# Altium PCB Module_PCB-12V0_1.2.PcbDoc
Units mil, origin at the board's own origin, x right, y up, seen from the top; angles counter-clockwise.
Board outline 2952.76 x 1181.1 mil, 2 copper layers (TopLayer, BottomLayer); 70 components, 40 nets, 211 pads, 102 vias.
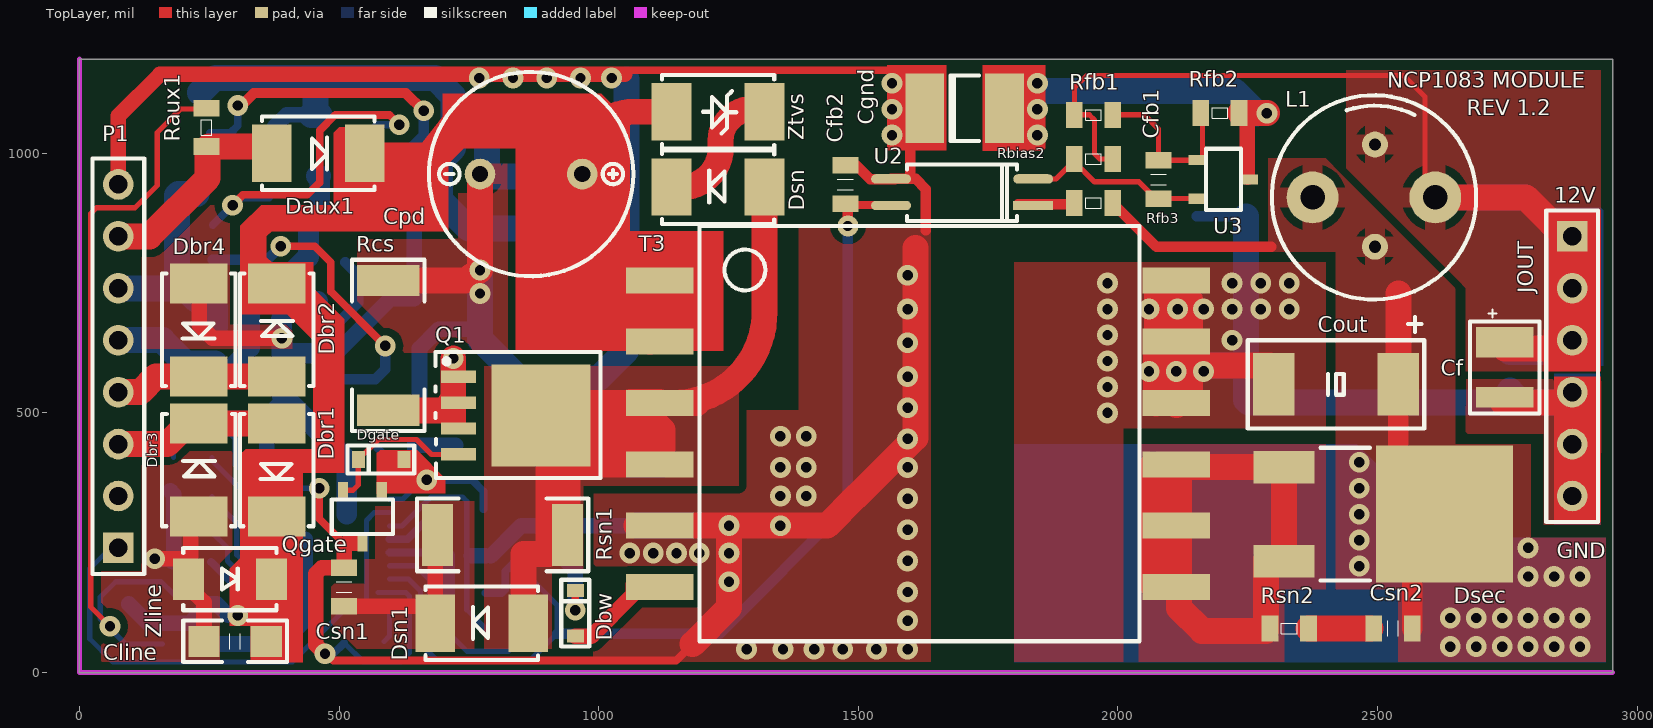
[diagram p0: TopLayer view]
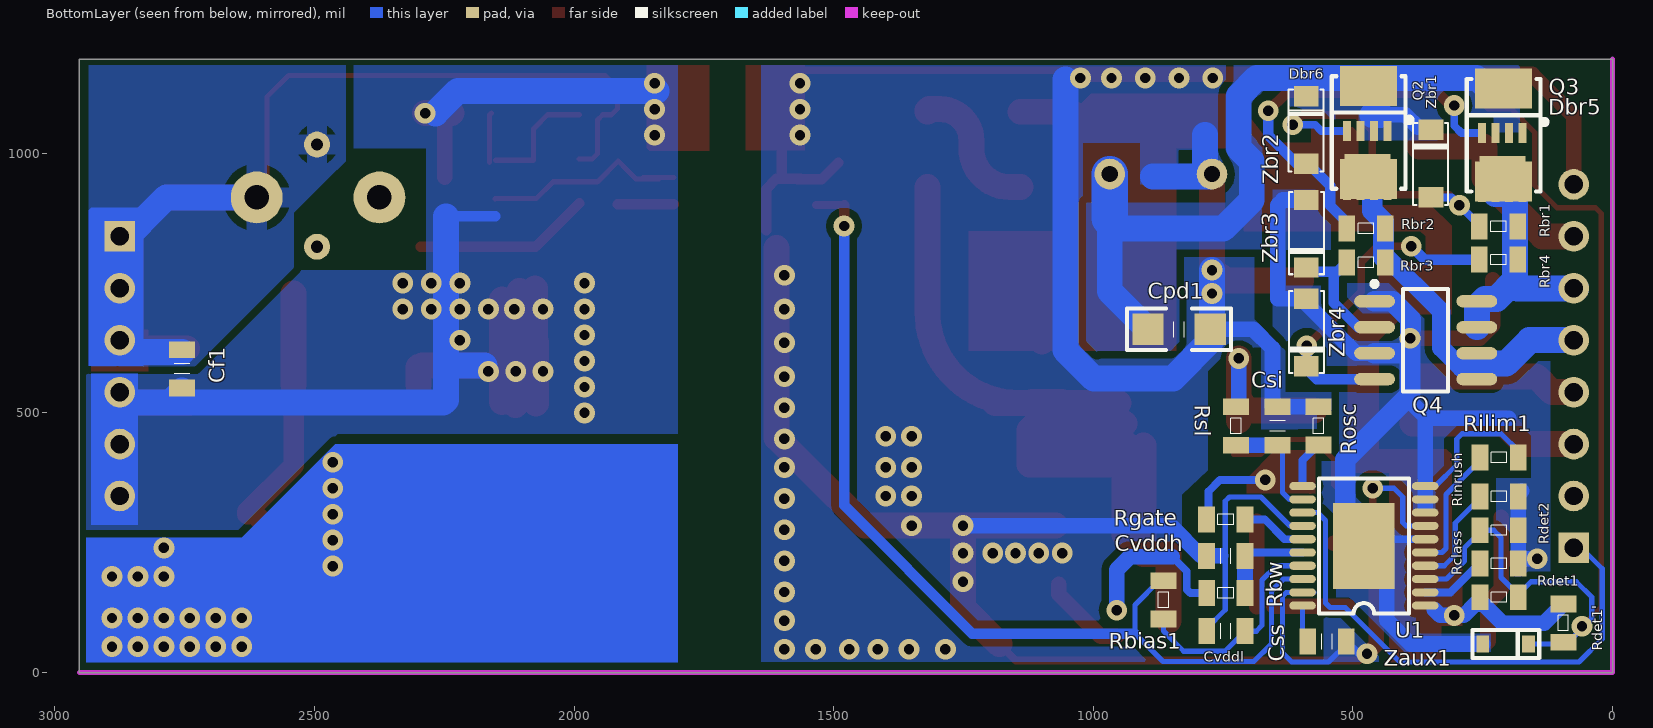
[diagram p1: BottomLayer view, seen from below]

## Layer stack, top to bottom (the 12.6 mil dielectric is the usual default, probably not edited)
TopLayer: signal copper 1.4
Dielectric: core 12.6, FR-4, Dk 4.8
BottomLayer: signal copper 1.4

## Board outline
0,0 0,1181.1 2952.76,1181.1 2952.76,0

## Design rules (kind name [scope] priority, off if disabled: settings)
Clearance Clearance_1 [inpolygon] p1: gap=15
Clearance [All] p2: gap=8
PasteMaskExpansion PasteMaskExpansion_1 [All] p1: expansion=0
PasteMaskExpansion [All] p2: expansion=0
PolygonConnect Thrucomp [All vs InThruComponent] p1: connectstyle=Relief reliefconductorwidth=40 reliefentries=4 polygonreliefangle="90 Angle"
PolygonConnect [All] p2: connectstyle=Direct reliefconductorwidth=10 reliefentries=4 polygonreliefangle="90 Angle"
RoutingVias [All] p1: holewidth=20 width=40 viastyle="Through Hole" minholewidth=20 minwidth=40 maxholewidth=20 maxwidth=40
ShortCircuit ShortCircuit_1 [All] p1: allowed=FALSE
ShortCircuit [All] p2: allowed=FALSE
SolderMaskExpansion SolderMaskExpansion_1 [All] p1: expansion=4
SolderMaskExpansion [All] p2: expansion=2
TestPointUsage [All] p1: valid=0 allowmultiple=FALSE
Testpoint [All] p1: side=7 testpointundercomponent=TRUE minsize=40 maxsize=100 preferedsize=60 minholesize=20 maxholesize=40 preferedholesize=32 testpointgrid=1 style=1001 order=0-112345678
UnRoutedNet UnRoutedNet_1 [All] p1:
UnRoutedNet [All] p2:
Width [All] p1: maxlimit=150 minlimit=8 preferedwidth=10
16 further rules are at their usual default settings.

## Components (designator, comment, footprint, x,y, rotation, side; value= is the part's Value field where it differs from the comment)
Cf "10u/20V" C-TANT-B 2745,530 r90 top
Cf1 "0.1u" 0805-C-S 2755,585 r270 bottom
Cfb1 "39n" 0805-C-S 2078.23,949.69 r270 top
Cfb2 "12n" 0805-C-S 1475,940 r90 top
Cgnd "2200p/2kV" 1812 1704.84,1086.5 r0 top
Cline "100n/100V" 1206-C 300,60 r0 top
Cout "68u/25V/55mR" C-TANT-E 2420,555 r180 top
Cpd "100u/63V" CRD10.0L17.0RM5.0 870,960 r180 top
Cpd1 "100n/100V" 1206-C 835,661 r0 bottom
Csi "NC" 0805-C-S 645,475 r90 bottom
Csn1 "100p/200V" 0805-C-S 510,165 r90 top
Csn2 "470p/200V" 0805-C-S 2530,85 r180 top
Css "47n" 0805-C-S 550,60 r180 bottom
Cvddh "2.2u/16V" 0805-C-S 745.06,224.61 r0 bottom
Cvddl "470n" 0805-C-S 745,80 r0 bottom
Daux1 "MBRS2H100T3G" 403A-03 460,1000 r0 top
Dbr1 "MBRS1100T3G" 403A-03 380,390 r270 top
Dbr2 "MBRS1100T3G" 403A-03 380,660 r90 top
Dbr3 "MBRS1100T3G" 403A-03 230,390 r90 top
Dbr4 "MBRS1100T3G" 403A-03 230,660 r270 top
Dbr5 "MBRS1100T3G" 403A-03_D 210,1035 r90 bottom
Dbr6 "MBRS1100T3G" 403A-03_D 470,1040 r90 bottom
Dbw "BAS16HT1G" SOD323 955,70 r90 top
Dgate "BAS16HT1G" SOD323 625,410 r180 top
Dsec "12CWQ06FNPBF" DPAK 2320,305 r270 top
Dsn "MURS120T3G" 403A-03 1230,935 r180 top
Dsn1 "MURS120T3G" 403A-03 775,95 r180 top
JOUT "Header 6" HDR1X6 2875,840 r270 top
L1 "10uH/3A" 10X12 2375,915 r0 top
P1 "Header 8" HDR1X8 75,240 r90 top
Q1 "Si7462DP" SOPP8 840,495 r0 top
Q2 "Si7113DN" "POWERPACK 1212-8" 472.44,984.25 r270 bottom
Q3 "Si7113DN" "POWERPACK 1212-8" 212.6,980.32 r270 bottom
Q4 "FDS3992" SO-8 360,640 r180 bottom
Qgate "BFT92" SOT23 545,300 r180 top
Raux1 "39k" 0805-R-S 245,1050 r90 top
Rbias1 "5.1k" 0805-R-S 865,140 r270 bottom
Rbias2 "20k" 0805-R-S 1953.23,989.06 r0 top
Rbr1 "150k" 0805-R-S 220,859 r180 bottom
Rbr2 "150k" 0805-R-S 475,855 r180 bottom
Rbr3 "150K" 0805-R-S 475,790 r0 bottom
Rbr4 "150K" 0805-R-S 220,795 r0 bottom
Rbw "75" 0805-R-S 745,153 r0 bottom
Rclass "22" 0805-R-S 218.46,210 r180 bottom
Rcs "0R1/2W" 2512-S 595,630 r270 top
Rdet1 "24.9k/0.1%" 0805-R-S 218.46,145 r180 bottom
Rdet1' "ADJ" 0805-R-S 95,95 r270 bottom
Rdet2 "845/0.1%" 0805-R-S 218.46,274.06 r180 bottom
Rfb1 "15k" 0805-R-S 1953.23,1074.06 r0 top
Rfb2 "3.9k" 0805-R-S 2196.34,1077.8 r180 top
Rfb3 "820" 0805-R-S 1953.23,904.06 r180 top
Rgate "10" 0805-R-S 745.06,294.61 r180 bottom
Rilim1 "44.2K" 0805-R-S 218.46,414.06 r0 bottom
Rinrush "120K" 0805-R-S 218.46,339.06 r0 bottom
Rosc "150K" 0805-R-S 566.24,475.16 r270 bottom
Rsl "5.1k" 0805-R-S 725,475 r270 bottom
Rsn1 "330/2W" 2512-S 815,265 r0 top
Rsn2 "75" 0805-R-S 2330,85 r180 top
T3 "SM-00112" NUFLUX 1615,460 r0 top
U1 "NCP1083" TSSOPEP20 479.06,243.98 r0 bottom
U2 "PS2801-1-F3-A" SSOP4 1700,925 r180 top
U3 "TL432BIDBZTG4" SOT23 2203.23,949.69 r270 top
Zaux1 "MM3Z3V3ST1G" SOD323 250,55 r180 bottom
Zbr1 "MMSZ16T1G" SOD123 350,915 r90 bottom
Zbr2 "MMSZ16T1G" SOD123 590,980 r90 bottom
Zbr3 "MMSZ16T1G" SOD123 590,910 r270 bottom
Zbr4 "MMSZ16T1G" SOD123 590,720 r270 bottom
Zline "1SMA58AT3G" SMA 290,180 r0 top
Ztvs "1SMB100AT3G" 403A-03 1230,1080 r0 top
? "Comment" COILCRAFT_IN 2495,820 r90 top

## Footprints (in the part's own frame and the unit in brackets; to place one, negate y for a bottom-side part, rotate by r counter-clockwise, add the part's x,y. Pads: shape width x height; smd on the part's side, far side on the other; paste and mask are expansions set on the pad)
10X12 [mm]
  round 2.54 hole 1.2: 1(0,0) 2(6,0)
  silkscreen extent -2,-5 8,5
403A-03 [mm] "Molded Diode, 2-Leads, Body 5.3x3.4mm, IPC Medium Density"
  rect 1.95x2.8 smd: 1(-2.275,0) 2(2.275,0)
  silkscreen extent -2.75,-1.8 2.75,1.8
403A-03_D [mm] "Molded Diode, 2-Leads, Body 5.3x3.4mm, IPC Medium Density"
  rect 1.95x2.8 smd: 1(-2.275,0) 2(2.275,0)
  silkscreen extent -2.75,-1.8 2.75,1.8
0805-C-S [mil]
  rect 32x50 smd: 1(-37,0) 2(37,0)
  silkscreen extent -10,-15 10,15
0805-R-S [mil]
  rect 32x50 smd: 1(-37,0) 2(37,0)
  silkscreen extent -15,-10 15,10
1206-C [mil]
  rect 60x60 smd: 1(-60,0) 2(60,0)
  silkscreen extent -100,-40 100,40
1812 [mm] "Chip Capacitor; Body 4.5 x 3.2 mm (LxW typ)"
  rect 1.9x3.4 smd: 1(-1.95,0) 2(1.95,0)
  silkscreen extent -0.7,-1.6 0.7,1.6
2512-S [mil]
  rect 60x120 smd: 1(-125,0) 2(125,0)
  silkscreen extent -165,-70 165,70
C-TANT-B [mm]
  rect 1.5x2.8 smd: 1(2.7,0)
  rect 1x2.8 smd: 2(0,0)
  silkscreen extent -0.8,-1.7 4.3,1.7
C-TANT-E [mil]
  rect 80x120 smd: 1(-120,0) 2(120,0)
  silkscreen extent -170,-85 170,85
COILCRAFT_IN [mm]
  round 1.27 hole 0.6: 1(0,0) 2(5,0)
  silkscreen extent 6.45,-1.94 6.9,1.38
CRD10.0L17.0RM5.0 [mm]
  round 1.5 hole 0.8: 1(-2.5,0) 2(2.5,0)
  silkscreen extent -5,-5 5,5
DPAK [mm]
  rect 1.6x3 smd: 1(-2.3,0) 3(2.3,0)
  rect 6.7x6.7 smd: 4(0,7.85)
  silkscreen extent -3.25,1.78 3.25,4.19
HDR1X6 [mm] "Connector; Header; 6 Position"
  rect 1.5x1.5 hole 0.9: 1(0,0)
  round 1.5 hole 0.9: 2(2.54,0) 3(5.08,0) 4(7.62,0) 5(10.16,0) 6(12.7,0)
  silkscreen extent -1.27,-1.27 13.97,1.27
HDR1X8 [mm] "Connector; Header; 8 Position"
  rect 1.5x1.5 hole 0.9: 1(0,0)
  round 1.5 hole 0.9: 2(2.54,0) 3(5.08,0) 4(7.62,0) 5(10.16,0) 6(12.7,0) 7(15.24,0) 8(17.78,0)
  silkscreen extent -1.27,-1.27 19.05,1.27
NUFLUX [mm]
  rect 3.3x1.27 smd: 1(-12.635,7.5) 2(-12.635,4.5) 3(-12.635,1.5) 4(-12.635,-1.5) 5(-12.635,-4.5) 6(-12.635,-7.5) 7(12.635,-7.5) 8(12.635,-4.5) 9(12.635,-1.5) 10(12.635,1.5) 11(12.635,4.5) 12(12.635,7.5)
  silkscreen extent -10.69,-10.15 10.83,10.16
"POWERPACK 1212-8" [mil] "PowerPAK 1212-8"
  rect 39x16 smd: 1(-58.75,39) 2(-58.75,13) 3(-58.75,-13) 4(-58.75,-39)
  rect 68x88 smd: 5(19.75,0.5)
  rect 30x16 smd: 5(58.75,-39) 6(58.75,-13) 7(58.75,13) 8(58.75,39)
  silkscreen extent -85,76 -75,86
SMA [mil]
  rect 60x80 smd: 1(-80,0) 2(80,0)
  silkscreen extent -90,-60 90,60
SO-8 [mm] "SOIC, 8-Leads, Body 4.9x3.9mm, Pitch 1.27mm, IPC Medium Density"
  oval 2x0.6 smd: 1(-2.5,1.905) 2(-2.5,0.635) 3(-2.5,-0.635) 4(-2.5,-1.905) 5(2.5,-1.905) 6(2.5,-0.635) 7(2.5,0.635) 8(2.5,1.905)
  silkscreen extent -2.63,-2.5 1.1,2.88
SOD123 [mm]
  rect 1x1.22 smd: 1(0,0) 2(3.302,0)
  silkscreen extent -0.38,-0.84 3.63,0.86
SOD323 [mm]
  rect 0.63x0.83 smd: 1(0,0) 2(2.23,0)
  silkscreen extent -0.51,-0.69 2.76,0.69
SOPP8 [mil] "PowerPAK SO-8"
  rect 68x24 smd: 1(-110,75) 2(-110,25) 3(-110,-25) 4(-110,-75) 5(110,-75) 6(110,-25) 7(110,25) 8(110,75)
  rect 190x196 smd: 5(49,0)
  silkscreen extent -155,-120 163,122
SOT23 [mm]
  rect 0.5x0.8 smd: 1(-0.95,-1.3) 2(0.95,-1.3) 3(0,1.3)
  silkscreen extent -1.5,-0.85 1.5,0.85
SSOP4 [mm]
  rect 1.95x0.46 smd: 1(-3.475,0.65)
  oval 1.95x0.46 smd: 2(-3.475,-0.65) 3(3.475,-0.65) 4(3.475,0.65)
  silkscreen extent -2.69,-1.35 2.69,1.41
TSSOPEP20 [mm]
  rect 3x4.2 smd: 0(0,0)
  oval 1.3x0.4 smd: 1(-3,2.925) 2(-3,2.275) 3(-3,1.625) 4(-3,0.975) 5(-3,0.325) 6(-3,-0.325) 7(-3,-0.975) 8(-3,-1.625) 9(-3,-2.275) 10(-3,-2.925) 11(3,-2.925) 12(3,-2.275) 13(3,-1.625) 14(3,-0.975) 15(3,-0.325) 16(3,0.325) 17(3,0.975) 18(3,1.625) 19(3,2.275) 20(3,2.925)
  silkscreen extent -2.2,-3.3 2.2,3.3

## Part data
Cf Cout Cpd: library part "CAP POL", "Capacitor Polar"
Cf1 Cfb1 Cfb2 Cgnd Cline Cpd1 Csi Csn1 Csn2 Css Cvddh Cvddl: library part CAP, "Capacitor"
Daux1 Dsn Dsn1: library part DIODE, "Diode"
Dbr1 Dbr2 Dbr3 Dbr4: library part "Diode 10TQ035", "Schottky Rectifier"
Dbr5 Dbr6: library part "Diode 10TQ035", "Diode Schottky"
Dbw Dgate: library part DIODES-KK, "Diodes Double"
Dsec Ztvs: library part DIODE_SCHOTTKY, "Diode Schottky"
JOUT: "Header, 6-Pin"
L1: library part INDUCTOR02, "Power Choke"
P1: "Header, 8-Pin"
Q1: library part "MOSFET N SOICN8 2", "MOSFET N-CHANNEL"
Q2 Q3: "P-Channel 30V (D-S)  MOSFET"
Q4: library part MOSFET_N_SOIC8, "MOSFET N-CHANNEL"
Qgate: library part PNP-BEC, "Transistor PNP"
Raux1 Rbias1 Rbias2 Rbr1 Rbr2 Rbr3 Rbr4 Rbw Rclass Rcs Rdet1 Rdet1' Rdet2 Rfb1 Rfb2 Rfb3 Rgate Rilim1 Rinrush Rosc Rsl Rsn1 Rsn2: library part RESISTOR_1, "Resistor"
T3: library part COILCRAFT_POE300_50L, "PoE Plus Transformer"
U1: library part AMIS80101, "Power over Ethernet controller"
U2: library part PS2801_1, "HIGH ISOLATION VOLTAGE SSOP PHOTOCOUPLER"
U3: library part TL431, "Programmable Shunt Voltage Reference"
Zaux1 Zbr1 Zbr2 Zbr3 Zbr4: library part DIODE_SCHOTTKY, "Diode Zener"
Zline: library part SMAJ58A, "Diode TRANSIL (TM)"

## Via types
v1: diameter 40, hole 20, TopLayer to BottomLayer, 102 vias

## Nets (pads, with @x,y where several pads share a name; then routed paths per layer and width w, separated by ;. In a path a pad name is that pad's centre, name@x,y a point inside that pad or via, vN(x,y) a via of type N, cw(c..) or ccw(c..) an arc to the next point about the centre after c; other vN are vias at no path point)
GND: Cfb2.2 Cgnd.1 Cpd1.1 Cpd.2 Csi.2 Csn1.2 Css.2 Cvddh.2 Cvddl.2 P1.8 Qgate.3 Rcs.1 Rosc.1 T3.5 U1.7 U1.14 U1.19 U2.3 | length 7950.4
  TopLayer w15: v1(462,354.75) 462,296 509.18,248.82 522.6,248.82 ; v1@474.5,37.5 489,23 1149,23 1180.79,54.79 ; Csn1.2 Csn1.2@510,213.82 ; v1@1012,1160 1580,1160 Cgnd.1@1625,1115
  TopLayer w20: Cfb2.2@1491.39,982 1523.39,950 U2.3@1570,950 ; U2.3 1610.41,950.59 1630,931 1630,852 ; U2.3@1600,953.86 Cgnd.1@1600,1065
  TopLayer w30: P1.8 75,1072 155,1152 1050,1152 ; 455,167 455,137 ; v1(473,36) 455,54 455,137 ; Qgate.3@537,248.82 522.6,248.82 513.82,248.82 510,245 510,213.82 Csn1.2 467,202 455,190 455,137
  TopLayer w50: Rcs.1@600,755 743,755 v1(771.58,775) Cpd.2 ; T3.5@1072.56,282.84 T3.5@1117.56,282.88 ; T3.5 v1@1251,282.84 ; 1180.79,54.79 1251,125 v1(1251,175) v1(1251,230) v1@1251,282.84 ; v1(1251,283) v1@1251,282.84 ; 1497,340 1439.84,282.84 v1(1350,282.84) v1@1251,282.84 ; 1497.5,339.5 1610,452 1610,818
  BottomLayer w10: U1.7 397.36,282.36 404,289 404,338 420.75,354.75 v1(462,354.75) ; Css.2@510,57 547,20 618,20 636,38 636,147 628.59,154.41 U1.19 U1.19@575.41,154.41 ; U1.14 621.36,282.36 677,338 738,338 746,330 746,121 782.06,84.94 Cvddl.2@782.06,79.61 ; Csi.2@644.84,512.16 Csi.2@655,522.31 ; Cvddh.2 Cvddh.2@792.61,224.61
  BottomLayer w15: v1(473,36) 489,36 Css.2@510,57 ; Cpd1.1 Cpd1.1@779,661
  BottomLayer w30: Rosc.1 Csi.2@655,512.16 ; Csi.2@655,512 655,624 692,661 Cpd1.1 ; 755,225 Cvddh.2 ; Cvddh.2@792.61,224.61 851,283 v1(1251,283)
  BottomLayer w50: v1(771.58,775) 771.58,641.42 847,566 999,566 1054,621 1054,1142 ; 785,1035 785,973.43 Cpd.2 776.58,955 885,955
  other v1: 1285,45 1355,45 1415,45 1470,45 1535,45 1595,45 1595,100 1595,155 1595,215 1060,230 1105,230 1150,230 1193.98,230 1595,275 1595,335 1350,340 1400,340 1350,395 1400,395 1595,395 1595,450 1350,455 1400,455 1595,510 1595,570 1595,635 1595,700 771.58,730 1595,765 1565,1035 1565,1085 1565,1135 770,1145 835,1145 900,1145 965,1145 1025,1145
GNDE: Cline.1 Dbr3.1 Dbr4.1 Q4.1 Q4.3 Rclass.2 Rdet2.2 Rilim1.1 Rinrush.1 U1.0 U1.6 U1.8 U1.9 U1.10 Zaux1.1 Zbr3.1 Zbr4.1 Zline.1 | length 2918.5
  TopLayer w30: v1(145,219) Zline.1@214.46,219 ; Dbr3.1@214.46,299.06 214.46,160.54 240,135 Cline.1 245,55 Cline.1@247,57 ; Dbr4.1@230.58,756.63 230.58,669.42 256,644 v1(390,644)
  BottomLayer w10: Rilim1.1 181.46,426.46 215,460 290,460 300,450 300,400 340.87,359.13 U1.10 U1.10@360.95,364.57 ; U1.0@506,302 U1.0@506,305
  BottomLayer w15: U1.6 U1.0@435,256.77 ; U1.10 360.95,364.57 360.95,384
  BottomLayer w30: v1(145,219) 173.52,219 Rclass.2@179.46,213.06 ; Rinrush.1@175,350 181.46,343.54 Rinrush.1 Rdet2.2 181.46,215.06 Rclass.2@176.52,220 ; 200,490 220,490 ; Zaux1.1 389,55 435,101 U1.0@435,256.77 ; 360.95,317 U1.9 U1.10 ; U1.10@360.95,364.57 360.95,384 360.95,487.05 358,490 ; 384,516 358,490 ; Q4.3 494,615 599,720 645,720 645,900 635,910 Zbr3.1 ; 220,490 230,490 ; 220,490 230,490 ; 230,490 358,490
  BottomLayer w40: v1@389.72,644 389.41,670.04 389.41,680.41 424,715 Q4.1 ; v1(390,644) 390,535 515,410 U1.0@515,305 ; 405,615 Q4.3
GNDO: Cf1.2 Cf.2 Cgnd.2 Cout.2 JOUT.4 JOUT.5 JOUT.6 Rfb2.1 T3.10 T3.11 T3.12 U3.3 | length 3044.1
  TopLayer w30: U3.3@2249.41,954 2249.41,1076.39
  TopLayer w50: Cgnd.2@1790,1120 1830,1120 ; T3.10@2073.44,518.06 T3.11@2073.44,636.16 ; T3.11@2075,636.16 T3.12@2075,740 ; T3.11@2105,616.89 T3.12@2105,735 ; T3.10@2112.44,515 T3.10 2112.44,597.16 2139,594.53 ; T3.10@2139,521 2139,594.53 ; 2139,718.84 2139,594.53 ; Rfb2.1@2236.34,1077.8 2253,1077.8 ; 2249.41,1076.39 2253,1077.8 ; v1@2287,1077.8 2253,1077.8 ; Cout.2 2300,588 2292.84,591.16 2173,591.16 2139,594.53 ; Cf.2@2742,520 2880,520 JOUT.6@2880,320
  BottomLayer w20: 2152,879 2260,879
  BottomLayer w50: v1@1841,1120 2224,1120 v1@2267,1077 ; v1@2173,591.16 2244.16,591.16 2247,594 ; 2247,878 2247,594 ; Cf1.2@2755,543 2778,520 ; JOUT.4@2880,520 2778,520 ; 2247,594 2247,525 2252,520 2778,520
  other v1: 1980,500 1980,550 2060,580 2112.44,580 2165,580 1980,600 2220,640 1980,650 1980,700 2060,700 2115,700 2165,700 2220,700 2275,700 2330,700 1980,750 2220,750 2275,750 2330,750 1845,1035 2287,1077 1845,1085 1845,1135
NCLASSAT: P1.1 U1.13 | length 1013.9
  BottomLayer w10: P1.1@70,250 20,200 20,65 65,20 410,20 515,125 544,125 553,134 553,293 567.95,307.95 U1.13
NetCf1_1: ?.2 Cf1.1 Cf.1 JOUT.1 JOUT.2 JOUT.3 L1.2 Rbias2.2 Rfb1.1 | length 2407.5
  TopLayer w10: Rbias2.2 1965,989.06 1955,999.06 1955,1064.06 1945,1074.06 1928,1074.06 1916.23,1085.83 1916.23,1126.23 1940,1150 2550,1150 2591.22,1108.78 L1.2@2591.22,915
  TopLayer w50: L1.2@2591.22,915 2785,915 JOUT.1@2880,820 ; Cf.1@2745,624.3 JOUT.3@2875.7,624.3 ; JOUT.1@2875.7,815.7 JOUT.1@2880,820 ; JOUT.3@2880,620 2880,720 JOUT.1@2880,820
  BottomLayer w50: L1.2@2591.22,915 2785,915 2880,820 2880,720 2880,620 2877,617 Cf1.1@2755,617
NetCfb1_1: Cfb1.1 Rfb1.2 Rfb2.2 U3.1 | length 330.1
  TopLayer w10: Rfb1.2 2050.94,1074.06 2078.23,1046.77 Cfb1.1 U3.1@2151.65,986.69 ; Rfb2.2 2163,1074.13 U3.1@2163,982
NetCfb1_2: Cfb1.2 Rbias2.1 U2.2 U3.2 | length 446
  TopLayer w10: U2.2@1808.15,953.39 U2.2@1867.39,953.39 ; U2.2 1880.59,950.59 1900,970 ; 1885.39,955.39 1900,970 ; Cfb1.2@2084.69,912.69 Cfb1.2 ; U3.2 2151.65,912.69 Cfb1.2 ; 1900,970 1915,985 1955,945 2040.69,945 2073,912.69 Cfb1.2
NetCfb2_1: Cfb2.1 Rbias1.1 U1.18 U2.4 | length 1892.1
  TopLayer w10: Cfb2.1@1480,900.2 Cfb2.1@1480,905
  TopLayer w15: Cfb2.1@1480,900.2 U2.4@1534.53,900.2
  TopLayer w20: v1(1480,860.04) Cfb2.1@1480,900.2
  BottomLayer w10: U1.18 634,180 657,157 657,55 691,21 866,21 920,75 920,130 Rbias1.1@873,177
  BottomLayer w20: 920,75 1233,75 1480,322 v1(1480,860.04)
NetCline_2: Cline.2 Cpd1.2 Cpd.1 Daux1.2 Dbr1.2 Dbr2.2 Dbr5.2 Dbr6.2 Q2.1 Q2.2 Q2.3 Q3.1 Q3.2 Q3.3 Rdet1'.1 Rdet1.1 T3.1 T3.2 U1.1 Zbr1.2 Zbr2.2 Zline.2 Ztvs.1 | length 2176.9
  TopLayer w50: Cpd.1@969.57,958.86 Cpd.1 968.43,980 cw(c1068.43,980) 1068.43,1080 Ztvs.1 ; T3.1@1072.84,755 1098.56,755.28 T3.2@1098.56,637.16
  BottomLayer w30: Rdet1'.1 132,95 212,95 249.06,132.06 264.46,132.06 286.52,110 v1(305,110) 332.05,110 343,120.95 ; 375,1050 399,1074 425,1074
  BottomLayer w50: Dbr5.2@232,1117 Dbr5.2@255,1140 ; Dbr5.2@263,1145 Dbr6.2@455,1145 ; 447.25,1073.75 462,1073.75 ; 455,1078 Dbr6.2@455,1145 ; Cpd1.2 968.43,734.42 968.43,875 948.43,855 750,855 695,910 695,985 720,1010 720,1110 685,1145 Dbr6.2@455,1145
  BottomLayer w70: 968.43,875 Cpd.1
NetCout_1: ?.1 Cout.1 Csn2.1 Dsec.4 L1.1 Rfb3.1 | length 1041.4
  TopLayer w20: Rfb3.1 2074.28,820 2295,820
  TopLayer w40: Cout.1 2540,399 2629.06,309.94 Dsec.4 ; Csn2.1 2567,257 Dsec.4@2615,305
  TopLayer w50: Cout.1 2540,730
  other v1: 2640,50 2690,50 2740,50 2790,50 2840,50 2890,50 2640,105 2690,105 2740,105 2790,105 2840,105 2890,105 2790,185 2840,185 2890,185 2465,205 2790,240 2465,255 2465,305 2465,355 2465,405
NetCsi_1: Csi.1 Rsl.2 U1.12 | length 230.9
  BottomLayer w10: U1.12 622.54,333.54 636,347 636,385 ; Csi.1@645,429 636,429 636,392 ; Rsl.2@719,429 Rsl.2@725,435 ; 636,385 636,392 ; 636,385 636,392
  BottomLayer w30: Csi.1 Rsl.2
NetCsn1_1: Csn1.1 Dsn1.2 Rsn1.1 | length 306.7
  TopLayer w30: Csn1.1 Dsn1.2@652.06,128 ; Dsn1.2@685.06,127 Rsn1.1@685.06,291.61
NetCsn2_2: Csn2.2 Rsn2.1 | length 119.8
  TopLayer w50: Rsn2.1 Csn2.2@2486.79,85
NetCss_1: Css.1 U1.20 | length 73
  BottomLayer w10: Css.1 597.17,70.17 U1.20
NetCvddh_1: Cvddh.1 Rbw.1 U1.16 | length 235.2
  BottomLayer w10: Rbw.1@703,173 Cvddh.1@703,223
  BottomLayer w15: U1.16 701.48,231.18 Cvddh.1
  BottomLayer w30: Rbw.1 Cvddh.1@708,224.55
NetCvddl_1: Cvddl.1 Rbias1.2 U1.17 | length 426.1
  BottomLayer w10: U1.17 647.41,205.59 675,178 675,91 686.39,79.61 708.06,79.61 746.66,41 826,41 865,80 Rbias1.2
NetDbr1_1: Dbr1.1 Dbr3.2 P1.3 | length 326.4
  TopLayer w50: P1.3 169,440 208.57,479.57 Dbr1.1 Dbr1.1@385,479.57
NetDbr2_1: Dbr2.1 Dbr4.2 P1.4 | length 322.6
  TopLayer w50: P1.4 117,540 147.43,570.43 Dbr2.1 Dbr2.1@385,570.43
NetDbr5_1: Dbr5.1 P1.6 Q3.5 Q3.6 Q3.7 Q3.8 Q4.7 Q4.8 Rbr1.2 Rbr4.1 | length 464.8
  BottomLayer w50: P1.6@70,740 P1.6 183,740 188,755 ; Q3.6 Q3.7 190.56,921.56 188,919 188,755 ; Q4.7 261.57,703.43 245.45,719.55 223.45,719.55 188,755
NetDbr6_1: Dbr6.1 P1.5 Q2.5 Q2.6 Q2.7 Q2.8 Q4.5 Q4.6 Rbr2.2 Rbr3.1 | length 666.6
  BottomLayer w35: 273.57,587 292,587 330,625 330,695 Rbr3.1@438,803
  BottomLayer w40: Rbr3.1@441,800 441,868 463,890 463,954.25 Q2.5@465,956.25 ; Q2.5@456.75,956.25 Q2.5@462,956.25
  BottomLayer w50: P1.5@80,640 160,640 205,595 261.57,595
NetDbw_1: Dbw.1 T3.6 | length 164.6
  TopLayer w30: Dbw.1 986,70 1067,151 T3.6@1067,170
NetDbw_2: Dbw.2 Rbw.2 | length 349.9
  TopLayer w15: v1(955,120) Dbw.2@955,159
  BottomLayer w15: Rbw.2 813,153 820,160 820,195 848,223
  BottomLayer w30: 848,223 930,223 955,198 v1(955,120)
NetDgate_1: Dgate.1 Qgate.1 Rgate.1 | length 289.2
  TopLayer w15: Qgate.1 625,393.78 Dgate.1 630,410 v1(669,371)
  BottomLayer w15: v1(669,371) 756.06,371 778.06,349 Rgate.1@778.06,314.61
NetDgate_2: Dgate.2 Q1.4 Qgate.2 | length 303.5
  TopLayer w10: Qgate.2 527.18,351.18 537.2,361.2 Dgate.2 576.2,449 649,449 678,420 Q1.4
NetDsec_1: Dsec.1 Dsec.3 Rsn2.2 T3.7 T3.8 T3.9 | length 1252.5
  TopLayer w50: T3.7@2067.44,167 2067.44,400.94 2095,373.39 ; Dsec.3@2285,219 2285,80 2162.16,80 2117.44,124.72 2117.44,395.55 Dsec.1 Dsec.3
NetDsn1_1: Dsn1.1 Dsn.1 Q1.5 Q1.6 Q1.7 Q1.8 Rsn1.2 T3.3 T3.4 | length 2026.4
  TopLayer w50: Dsn1.1@855,100 855,228 903,228 ; Q1.5@934,438 1117.56,438 ; 935,385 940,380 Rsn1.2@940,270 ; Rsn1.2 903,228 ; Q1.5@940,480 1110,480 1122.56,467.44 1122.56,401 939,401 903,437 903,228 ; Q1.5@951.95,519.06 T3.3@1072.56,519.06 ; T3.3@1055,515 1061,521 T3.3@1117.56,521 ; 1189.05,519.06 T3.3 1144.07,519.06 ccw(c1144.07,694.55) 1319.57,694.55 Dsn.1
NetDsn_2: Dsn.2 Ztvs.2 | length 274.4
  TopLayer w50: Dsn.2 1160.87,935 ccw(c1160.87,1009.13) 1235,1009.13 1235,1025 cw(c1295,1025) 1295,1085 1314.57,1085 cw(c1314.57,1080) Ztvs.2
NetQ1_1: Q1.1 Q1.2 Q1.3 Rcs.2 Rsl.1 | length 370.1
  TopLayer w50: Rcs.2@575,505 715,505 Q1.2@715,520 ; 720,485 v1(720,605)
  BottomLayer w30: v1(720,605) 720,517 Rsl.1
NetQ2_4: Q2.4 Rbr1.1 Zbr1.1 | length 699
  TopLayer w15: v1(295,900) 315,920 439,920 463,944 463,1044 493,1074 597,1074 v1(616,1055)
  BottomLayer w15: Rbr1.1@257,862 v1(295,900) 310,915 360,915 Zbr1.1@365,915 ; Q2.4 561,1043 573,1055 v1(616,1055)
NetQ3_4: Q3.4 Rbr2.1 Zbr2.1 | length 767.3
  TopLayer w20: v1@305,1085 336,1116 629,1116 v1(663,1082)
  BottomLayer w15: Q3.4 291.06,1039.06 305,1053 v1(305,1092)
  BottomLayer w20: Rbr2.1@512,865 512,867 544,899 544,937.66 586.34,980 Zbr2.1 Zbr2.1@600,980 ; Zbr2.1@608,980 663,1035 v1(663,1082)
NetQ4_2: Q4.2 Rbr3.2 Zbr3.2 | length 232.4
  BottomLayer w20: Q4.2 490,665 537,712 537,765 544,772 ; Rbr3.2 530,772 544,772 ; Zbr3.2@576,772 544,772
NetQ4_4: Q4.4 Rbr4.2 Zbr4.2 | length 641.4
  TopLayer w15: v1(388,821) 453,821 484,790 484,734 v1(589,629)
  BottomLayer w20: Rbr4.2 362,795 v1(388,821) ; v1@385.66,824.39 v1@388,826 ; Q4.4 570,565 589,584 v1(589,629)
NetRaux1_2: Raux1.2 Rdet1'.2 Rdet1.2 Rdet2.1 U1.3 Zaux1.2 | length 1899.3
  TopLayer w10: v1(59,89) 22,126 22,884 33,895 107,895 150,938 150,1040 195,1085 240,1085 Raux1.2@250,1095
  BottomLayer w10: Rdet1'.2@86,58 Rdet1'.2@78.46,65.54 ; Rdet1'.2@95,55 Rdet1'.2@114,55 ; Zaux1.2@160,55 Rdet1'.2@114,55 ; Rdet2.1@249.06,274.06 Rdet2.1 ; U1.3 320,180 285,215 285,240.38 255.46,269.92 Rdet2.1 ; Rdet1'.2@78.46,65.54 89,55 Rdet1'.2@114,55 ; Rdet1'.2@78.46,65.54 40,104 40,145 70,175 157,175 182,150 215,183 215,260 229.06,274.06 Rdet2.1
NetRclass_1: Rclass.1 U1.2 | length 131.8
  BottomLayer w15: Rclass.1@253.46,213.06 312.11,154.41 U1.2
NetRfb3_2: Rfb3.2 U2.1 | length 108.1
  TopLayer w20: U2.1@1808.15,902.2 Rfb3.2@1916.23,902.2
NetRgate_2: Rgate.2 U1.15 | length 126.7
  BottomLayer w15: U1.15 631.77,256.77 670,295 Rgate.2@708.06,295
NetRilim1_2: Rilim1.2 U1.5 | length 245.4
  BottomLayer w10: Rilim1.2 255.46,408.54 321,343 321,239 328.82,231.18 U1.5
NetRinrush_2: Rinrush.2 U1.4 | length 198.6
  BottomLayer w10: Rinrush.2 255.46,335.54 303,288 303,227 324.41,205.59 U1.4
NetRosc_2: Rosc.2 U1.11 | length 82.5
  BottomLayer w15: Rosc.2@574,432 597.17,408.83 U1.11
VAUX(+): Daux1.1 P1.7 Raux1.1 | length 402.6
  TopLayer w50: P1.7 135,840 247,952 247,1010 250,1013 Daux1.1@372,1013
pads on no net: P1.2

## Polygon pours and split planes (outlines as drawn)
GND on TopLayer "BottomLayerGNDE" (solid, remove dead copper, pour order 1001): 535,615 535,835 730,835 730,985 745,1000 781.43,1002 824,1002 826,664 825,617.46
NetCf1_1 on TopLayer "BottomLayerGNDE" (solid, remove dead copper, pour order 1004): 2670,580 2930,580 2930,1160 2440,1160 2440,970 2670,740
NetDsn1_1 on TopLayer "BottomLayerGNDE" (solid, remove dead copper, pour order 1003): 780,40 910,40 910,200 970,200 970,360 1270,360 1270,590 780,590
GNDO on TopLayer "BottomLayerGNDE" (solid, remove dead copper, pour order 1001): 2010,20 1800,20 1800,790 2400,790 2400,470 2010,470
NetDsec_1 on TopLayer "BottomLayerGNDE" (solid, remove dead copper, pour order 1000): 2040,50 2040,440 2400,440 2400,160 2320,160 2320,50 2320,20 2040,20 2040,50
NetCout_1 on TopLayer "BottomLayerGNDE" (solid, remove dead copper, pour order 1002): 2540,20 2940,20 2940,260 2795,260 2795,440 2650,440 2650,740 2400,990 2290,990 2290,810 2420,810 2420,160 2540,160
GNDO on TopLayer "BottomLayerGNDE" (solid, remove dead copper, pour order 1003): 2820,285 2930,285 2931.23,575.34 2671.23,575.34 2670,460 2820,460
GNDE on TopLayer "BottomLayerGNDE" (solid, remove dead copper, pour order 1000): 20,20 270,20 270,210 300,240 300,500 410,610 410,660 400,670 290,670 290,870 260,900 20,900
GND on TopLayer "BottomLayerGNDE" (solid, remove dead copper, pour order 1004): 990,10 990.97,355 1170,360 1285,360 1285,505 1385,505 1385,860.04 1510,860.04 1550,860 1640,860.04 1640,10
NetCsn1_1 on TopLayer "BottomLayerGNDE" (solid, remove dead copper, pour order 1002): 480,100 540,40 760,40 760,330 570,330 570,218 550,218 550,180 500,180 480,160
GND on BottomLayer "BottomLayerGNDE" (solid, remove dead copper, pour order 1008): 990,210 990,10 1640,10 1640,1170 1261.64,1170 1261.64,490 990,210
GNDO on BottomLayer "BottomLayerGNDE" (solid, remove dead copper, pour order 1005): 1800,460 1800,1170 2940,1170 2940,275 2640,275 2455,460
NetCf1_1 on BottomLayer "BottomLayerGNDE" (solid, remove dead copper, pour order 1000): 2935,590 2730,590 2690,630 2540,780 2540,885 2475,950 2440,985 2440,1075 2440,1170 2935,1170 2935,590
GNDE on BottomLayer "BottomLayerGNDE" (solid, remove dead copper, pour order 1005): 20,20 560,20 560,550 655,645 655,930 20,930
GND on BottomLayer "BottomLayerGNDE" (solid, remove dead copper, pour order 1001): 749.12,921.11 883.89,921.11 885,920 910,920 910,1005 910,1020 1005,1020 1080,1020 1085,1025 1085,1160 1075,1170 1020,1170 745,1170 745,1135 745,1130 760,1115 751.58,1106.57 751.58,920.09
NetCline_2 on BottomLayer "BottomLayerGNDE" (solid, remove dead copper, pour order 1002): 920,920 920,1015 1015,1015 1015,639.07 993.39,617.46 991.2,619.65 850,619.65 850,621 840,631 835,636 835,725 840,730 840,815 675,815 675,1015 700,1040 700,1092.5 672.5,1120 655,1120 627,1120 624,1123 624,1085 560,1085 530,1055 500,1025 360,1025 178.44,1025 178.44,1166.56 181.88,1170 735,1170 735,1135 745,1125 750,1120 750,1015 750,995 735,980 730,975 730,945 730,941.66 751.58,920.09 751.66,920 920,920
GND on BottomLayer "BottomLayerGNDE" (solid, remove dead copper, pour order 1006): 450,10 450,50 570,170 570,400 540,430 540,540 630,540 630,620 690,680 690,800 830,800 830,630 840,620 1000,620 1020,640 1020,1170 1310,1170 1310,10
NetCf1_1 on Mechanical4 "BottomLayerGNDE" (solid, remove dead copper): 2670,590 2670,740 2230,1180 2930,1170 2930,590

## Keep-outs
KeepOutLayer:
  lines w10: 0,1181.1 0,0 2952.76,0
  text ".Layer_Name" at 1600,-70 h40

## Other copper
TopLayer:
  rectangle net GND: 1555,1005 1670,1170
  region net GNDO: 1740,1170 1740,1005 1855,1005 1860,1010 1860,1170
  region net NetCf1_1: 2930,580 2930,660 2820,660 2820,580
  region net NetCf1_1: 2830,590 2830,890 2930,890 2930,590
  region net GNDO: 2840,290 2930,290 2930,570 2840,570
  pour cut-out: 22,200 110,200 120,210 120,820 22,820
  pour cut-out: 410,623.82 410,560 170.43,560 159.88,570.55 120,590 120,623.82
  pour cut-out: 42.39,200 42.39,22.39 40,20 10,20 10,200
  region net NetCline_2: 330,20 330,90 290,90 290,200 310,220 310,420 320,430 450,430 450,640 510,640 510,385 430,385 430,20
  region net NetCline_2: 450,640 400,690 310,690 310,860 350,900 490,900 490,1040 500,1050 580,1050 580,1020 660,1020 700,1070 700,1115 1005,1115 1060,1060 1060,850 1240,850 1240,620 840,620 840,1010 740,1010 710,980 710,850 370,850 360,840 360,800 370,790 450,790 450,740 510,680 510,640
  pour cut-out: 824.71,980 824.71,994.71 804.33,994.71 800,990.37 800,980
  pour cut-out: 746,923 726,923 726,938 746,938
  pour cut-out: 1055,205 983,205 983,119 982,118 1067,118 1081,132 1079,134 1079,181
  region net NetDgate_1: 572,345 705,345 705,373.46 650.46,428 579,428 573,422 573,346
  text ".Layer_Name" at 100,-170 h40
BottomLayer:
  pour cut-out: 174.44,1040.25 270.25,1040.25 284.81,1054.81 337.5,1054.81 337.5,1017.5 326,1006 171,1006 171,1036.81
  region net GNDO: 2840,575 2930,575 2930,285 2840,285
  region net NetCout_1: 2940,20 1800,20 1800,440 2460,440 2640,260 2940,260
  pour cut-out: 526.24,454.06 526.24,505.09 564.91,505.09 570,500 570,450 530.29,450
  pour cut-out: 440,750 610,750 610,810 605.32,814.68 445.68,814.68 440,809
  pour cut-out: 120,190 120,680 110,690 10,690 10,200 20,190
  pour cut-out: 556,100 556,116 560,120 580,120 580,103.23 576.77,100
  pour cut-out: 830,60 830,342 780,390 780,580 734.38,624.2 677,626 677,63 680,60 681.39,61.39 817.55,61.39
  pour cut-out: 2525.87,774.15 2525.02,775 2285,775 2285,1010 2425,1010 2425,973.37 2525.87,872.5
  region net NetCf1_1: 2935,590.87 2935,890.01 2930.01,895 2830,895 2830,590 2830.87,590.87
  pour cut-out: 745.29,904.71 745,905 745,921.8 746.4,923.2 771.57,940 910,940 925.29,935.29 925.58,935 1013.65,934.52 1013.65,904.71
  pour cut-out: 235,74.19 234.49,74.7 369.7,74.7 378.66,83.66 378.66,105.5 240.5,105.5 235,100
  pour cut-out: 235,74.19 235,30 185,30 185,70 190,75 190.81,74.19
  pour cut-out: 410,325 482.17,325 494.8,337.62 494.8,342.47 427.47,342.47
  pour cut-out: 157.46,374.06 ccw(c157.46,373.06) 156.46,373.06 156.46,456.46 175,475 300,475 325,450 325,398.03 349.13,373.9 376.69,373.9 376.69,350 375.89,350.8 324.2,350.8 300,375 299.06,374.06
  text ".Layer_Name" at 4040,-165 h40
  text "AKIT80101_1_TSP_2.0   071206" at 1625,-290 h50
MultiLayer:
  text ".Layer_Name" at 600,-70 h40

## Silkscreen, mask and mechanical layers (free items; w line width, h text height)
TopOverlay:
  lines w7.87: 1201,1080 1218,1080 ; 1213,966 1213,967 ; 1236.5,1038.37 1247,1048.87 ; 1247,1079 1265,1079 ; 1247,1110 1249.5,1112.5 1254.5,1117.5 1257,1120 ; 2559,671 2585,671 ; 2572,656 2572,685
  text "NCP1083 MODULE" at 2519,1126 h30
  text "REV 1.2" at 2672,1073 h30
  text "12V" at 2840,905 h30
  text "GND" at 2845,220 h30
  text ".Layer_Name" at 1100,-170 h40
BottomOverlay:
  text ".Layer_Name" at 3040,-165 h40
  text "NCP1081SPCEVB_1.0   AJ071206" at 4035,-265 h40
TopPaste:
  text ".Layer_Name" at 1600,-170 h40
BottomPaste:
  text ".Layer_Name" at 2540,-165 h40
TopSolder:
  text ".Layer_Name" at 2100,-170 h40
BottomSolder:
  text ".Layer_Name" at 3100,-170 h40
DrillGuide:
  text ".Layer_Name" at 1100,-70 h40
Mechanical1:
  the board outline again, w10
  text "03:15 PM" at 685,1285 h60
  text "18-12-08" at 110,1280 h60
  text ".Layer_Name" at 100,-70 h40
Mechanical5:
  text ".Layer_Name" at 600,-170 h40
Mechanical6:
  text ".Layer_Name" at 3540,-165 h40
DrillDrawing:
  text ".LEGEND" at 3045,367 h30
  text "Drill Drawing." at 3045,273 h30
  text ".Layer_Name" at 2100,-70 h40

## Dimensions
0,0 to -78.74,1181.1 on Mechanical2
2952.76,1181.1 to 0,1181.1 on Mechanical2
